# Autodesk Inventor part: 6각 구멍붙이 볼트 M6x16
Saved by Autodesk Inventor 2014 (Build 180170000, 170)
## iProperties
Created: 2026-09
Part Number: 6각 구멍붙이 볼트 M6x16
Material: 강철, 연강
Document SubType Name: Modeling
Designer: dg
Density: 7.86 g/cm^3
Appearance: 강철
Mass: 6.59379 g
Surface Area: 6.88702 cm^2
Volume: 0.838904 cm^3
Author: jhkim
Description: 6각머리 태핑 나사
Creation Date: 2026-08-26
Sending System: Autodesk Inventor 2027
Preprocessor: ST-DEVELOPER v20.1
Author: dg
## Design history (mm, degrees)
node "6각 구멍붙이 볼트 M6x161"
body "Solid1"
node "기준1"
